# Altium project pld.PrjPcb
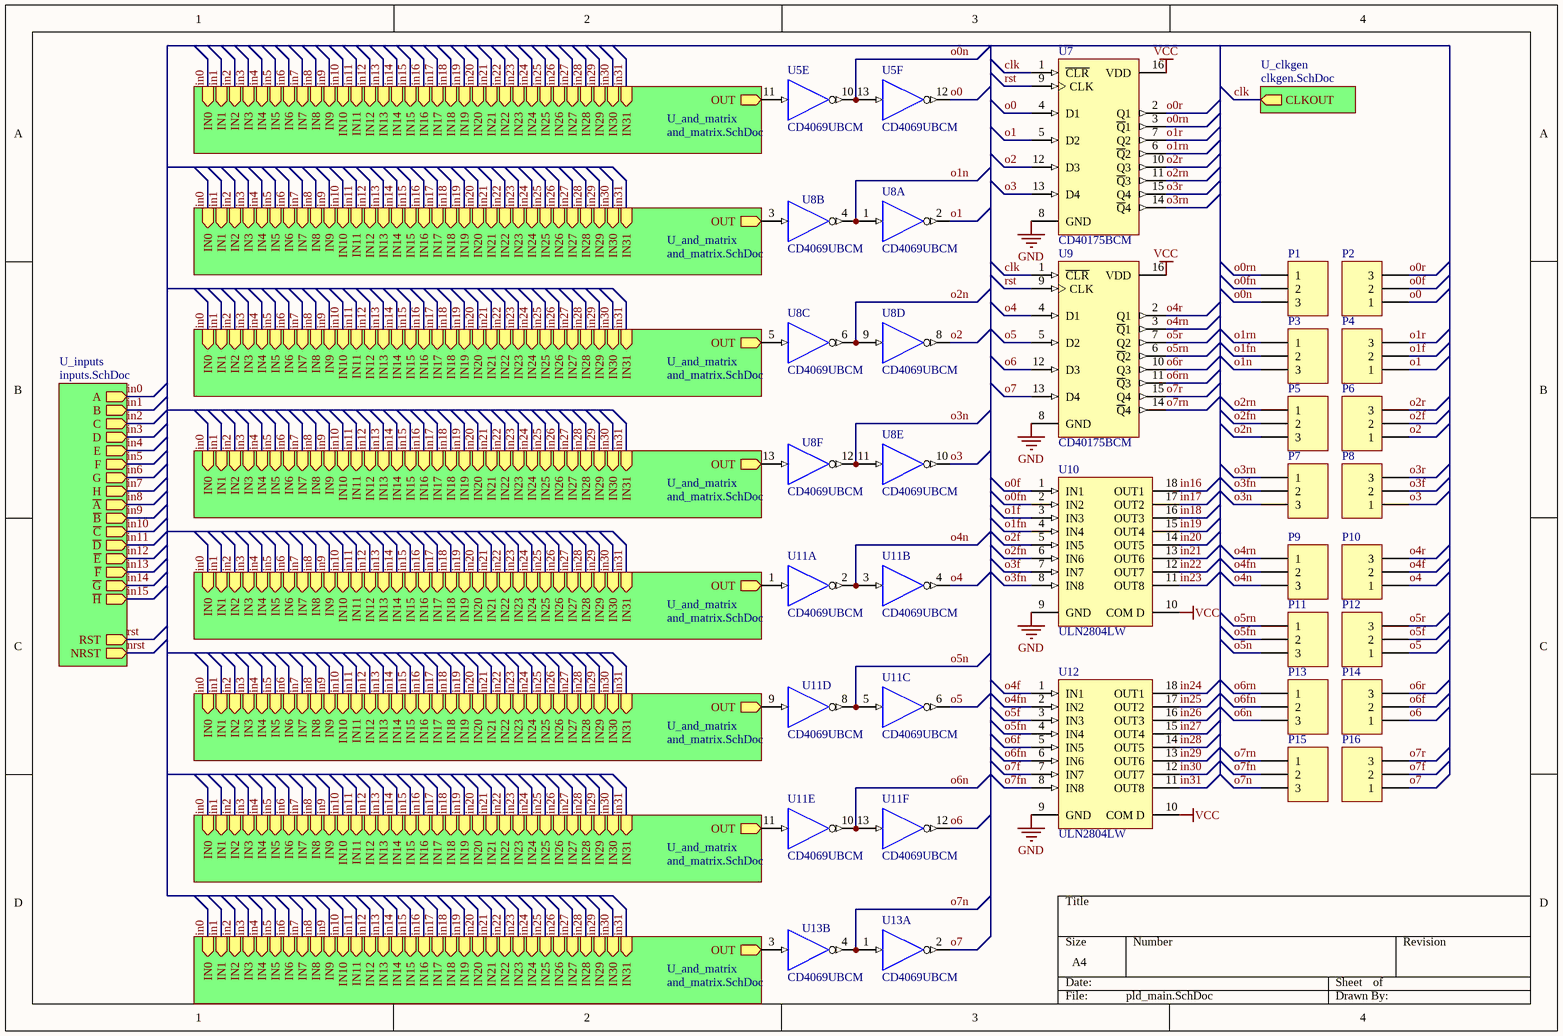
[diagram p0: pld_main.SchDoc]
4 sheets, 190 parts. Net scope: hierarchical (ports join the sheet entries above them; power ports are global).
Board file: pldpcb.PcbDoc
Sheets:
  pld_main.SchDoc
    U_inputs = inputs.SchDoc
    U_and_matrix = and_matrix.SchDoc
    U_and_matrix = and_matrix.SchDoc
    U_and_matrix = and_matrix.SchDoc
    U_and_matrix = and_matrix.SchDoc
    U_and_matrix = and_matrix.SchDoc
    U_and_matrix = and_matrix.SchDoc
    U_and_matrix = and_matrix.SchDoc
    U_and_matrix = and_matrix.SchDoc
    U_clkgen = clkgen.SchDoc

## Sheet pld_main.SchDoc
size A4

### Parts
(Parts that share a designator on the sheet are numbered #1, #2 ... from top to bottom, then left to right.)
P1  Header 3  [HDR1X3]  (value not drawn)
P2  Header 3  [HDR1X3]  (value not drawn)
P3  Header 3  [HDR1X3]  (value not drawn)
P4  Header 3  [HDR1X3]  (value not drawn)
P5  Header 3  [HDR1X3]  (value not drawn)
P6  Header 3  [HDR1X3]  (value not drawn)
P7  Header 3  [HDR1X3]  (value not drawn)
P8  Header 3  [HDR1X3]  (value not drawn)
P9  Header 3  [HDR1X3]  (value not drawn)
P10  Header 3  [HDR1X3]  (value not drawn)
P11  Header 3  [HDR1X3]  (value not drawn)
P12  Header 3  [HDR1X3]  (value not drawn)
P13  Header 3  [HDR1X3]  (value not drawn)
P14  Header 3  [HDR1X3]  (value not drawn)
P15  Header 3  [HDR1X3]  (value not drawn)
P16  Header 3  [HDR1X3]  (value not drawn)
U5#1  CD4069UBCM  [M14A_N]  (parts E,F of 6)
U7  CD40175BCM  [M16A_N]
U8  CD4069UBCM  [M14A_N]  (parts A,B,C,D,E,F of 6)
U9  CD40175BCM  [M16A_N]
U10  ULN2804LW  [LW18_L]
U11  CD4069UBCM  [M14A_N]  (parts A,B,C,D,E,F of 6)
U12  ULN2804LW  [LW18_L]
U13  CD4069UBCM  [M14A_N]  (parts A,B of 6)

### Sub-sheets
U_and_matrix = and_matrix.SchDoc: IN0 (in), IN1 (in), IN2 (in), IN3 (in), IN4 (in), IN5 (in), IN6 (in), IN7 (in), IN8 (in), IN9 (in), IN10 (in), IN11 (in), IN12 (in), IN13 (in), IN14 (in), IN15 (in), IN16 (in), IN17 (in), IN18 (in), IN19 (in), IN20 (in), IN21 (in), IN22 (in), IN23 (in), IN24 (in), IN25 (in), IN26 (in), IN27 (in), IN28 (in), IN29 (in), IN30 (in), IN31 (in), OUT (out)
U_and_matrix = and_matrix.SchDoc: IN0 (in), IN1 (in), IN2 (in), IN3 (in), IN4 (in), IN5 (in), IN6 (in), IN7 (in), IN8 (in), IN9 (in), IN10 (in), IN11 (in), IN12 (in), IN13 (in), IN14 (in), IN15 (in), IN16 (in), IN17 (in), IN18 (in), IN19 (in), IN20 (in), IN21 (in), IN22 (in), IN23 (in), IN24 (in), IN25 (in), IN26 (in), IN27 (in), IN28 (in), IN29 (in), IN30 (in), IN31 (in), OUT (out)
U_and_matrix = and_matrix.SchDoc: IN0 (in), IN1 (in), IN2 (in), IN3 (in), IN4 (in), IN5 (in), IN6 (in), IN7 (in), IN8 (in), IN9 (in), IN10 (in), IN11 (in), IN12 (in), IN13 (in), IN14 (in), IN15 (in), IN16 (in), IN17 (in), IN18 (in), IN19 (in), IN20 (in), IN21 (in), IN22 (in), IN23 (in), IN24 (in), IN25 (in), IN26 (in), IN27 (in), IN28 (in), IN29 (in), IN30 (in), IN31 (in), OUT (out)
U_and_matrix = and_matrix.SchDoc: IN0 (in), IN1 (in), IN2 (in), IN3 (in), IN4 (in), IN5 (in), IN6 (in), IN7 (in), IN8 (in), IN9 (in), IN10 (in), IN11 (in), IN12 (in), IN13 (in), IN14 (in), IN15 (in), IN16 (in), IN17 (in), IN18 (in), IN19 (in), IN20 (in), IN21 (in), IN22 (in), IN23 (in), IN24 (in), IN25 (in), IN26 (in), IN27 (in), IN28 (in), IN29 (in), IN30 (in), IN31 (in), OUT (out)
U_and_matrix = and_matrix.SchDoc: IN0 (in), IN1 (in), IN2 (in), IN3 (in), IN4 (in), IN5 (in), IN6 (in), IN7 (in), IN8 (in), IN9 (in), IN10 (in), IN11 (in), IN12 (in), IN13 (in), IN14 (in), IN15 (in), IN16 (in), IN17 (in), IN18 (in), IN19 (in), IN20 (in), IN21 (in), IN22 (in), IN23 (in), IN24 (in), IN25 (in), IN26 (in), IN27 (in), IN28 (in), IN29 (in), IN30 (in), IN31 (in), OUT (out)
U_and_matrix = and_matrix.SchDoc: IN0 (in), IN1 (in), IN2 (in), IN3 (in), IN4 (in), IN5 (in), IN6 (in), IN7 (in), IN8 (in), IN9 (in), IN10 (in), IN11 (in), IN12 (in), IN13 (in), IN14 (in), IN15 (in), IN16 (in), IN17 (in), IN18 (in), IN19 (in), IN20 (in), IN21 (in), IN22 (in), IN23 (in), IN24 (in), IN25 (in), IN26 (in), IN27 (in), IN28 (in), IN29 (in), IN30 (in), IN31 (in), OUT (out)
U_and_matrix = and_matrix.SchDoc: IN0 (in), IN1 (in), IN2 (in), IN3 (in), IN4 (in), IN5 (in), IN6 (in), IN7 (in), IN8 (in), IN9 (in), IN10 (in), IN11 (in), IN12 (in), IN13 (in), IN14 (in), IN15 (in), IN16 (in), IN17 (in), IN18 (in), IN19 (in), IN20 (in), IN21 (in), IN22 (in), IN23 (in), IN24 (in), IN25 (in), IN26 (in), IN27 (in), IN28 (in), IN29 (in), IN30 (in), IN31 (in), OUT (out)
U_and_matrix = and_matrix.SchDoc: IN0 (in), IN1 (in), IN2 (in), IN3 (in), IN4 (in), IN5 (in), IN6 (in), IN7 (in), IN8 (in), IN9 (in), IN10 (in), IN11 (in), IN12 (in), IN13 (in), IN14 (in), IN15 (in), IN16 (in), IN17 (in), IN18 (in), IN19 (in), IN20 (in), IN21 (in), IN22 (in), IN23 (in), IN24 (in), IN25 (in), IN26 (in), IN27 (in), IN28 (in), IN29 (in), IN30 (in), IN31 (in), OUT (out)
U_clkgen = clkgen.SchDoc: CLKOUT (out)
U_inputs = inputs.SchDoc: A (out), B (out), C (out), D (out), E (out), F (out), G (out), H (out), ~{A} (out), ~{B} (out), ~{C} (out), ~{D} (out), ~{E} (out), ~{F} (out), ~{G} (out), ~{H} (out), RST (out), NRST (out)

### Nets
GND: U5#1.7(GND) U7.8(GND) U8.7(GND) U9.8(GND) U10.9(GND) U11.7(GND) U12.9(GND) U13.7(GND)
VCC: U7.16(VDD) U9.16(VDD) U10.10(COM_D) U12.10(COM_D)
VDD: U5#1.14(VDD) U8.14(VDD) U11.14(VDD) U13.14(VDD)
clk: U7.1(~{CLR}) U9.1(~{CLR}) ; sheet U_clkgen/CLKOUT
in0: sheet U_inputs/A, sheet U_and_matrix/IN0, sheet U_and_matrix/IN0, sheet U_and_matrix/IN0, sheet U_and_matrix/IN0, sheet U_and_matrix/IN0, sheet U_and_matrix/IN0, sheet U_and_matrix/IN0, sheet U_and_matrix/IN0
in1: sheet U_inputs/B, sheet U_and_matrix/IN1, sheet U_and_matrix/IN1, sheet U_and_matrix/IN1, sheet U_and_matrix/IN1, sheet U_and_matrix/IN1, sheet U_and_matrix/IN1, sheet U_and_matrix/IN1, sheet U_and_matrix/IN1
in2: sheet U_inputs/C, sheet U_and_matrix/IN2, sheet U_and_matrix/IN2, sheet U_and_matrix/IN2, sheet U_and_matrix/IN2, sheet U_and_matrix/IN2, sheet U_and_matrix/IN2, sheet U_and_matrix/IN2, sheet U_and_matrix/IN2
in3: sheet U_inputs/D, sheet U_and_matrix/IN3, sheet U_and_matrix/IN3, sheet U_and_matrix/IN3, sheet U_and_matrix/IN3, sheet U_and_matrix/IN3, sheet U_and_matrix/IN3, sheet U_and_matrix/IN3, sheet U_and_matrix/IN3
in4: sheet U_inputs/E, sheet U_and_matrix/IN4, sheet U_and_matrix/IN4, sheet U_and_matrix/IN4, sheet U_and_matrix/IN4, sheet U_and_matrix/IN4, sheet U_and_matrix/IN4, sheet U_and_matrix/IN4, sheet U_and_matrix/IN4
in5: sheet U_inputs/F, sheet U_and_matrix/IN5, sheet U_and_matrix/IN5, sheet U_and_matrix/IN5, sheet U_and_matrix/IN5, sheet U_and_matrix/IN5, sheet U_and_matrix/IN5, sheet U_and_matrix/IN5, sheet U_and_matrix/IN5
in6: sheet U_inputs/G, sheet U_and_matrix/IN6, sheet U_and_matrix/IN6, sheet U_and_matrix/IN6, sheet U_and_matrix/IN6, sheet U_and_matrix/IN6, sheet U_and_matrix/IN6, sheet U_and_matrix/IN6, sheet U_and_matrix/IN6
in7: sheet U_inputs/H, sheet U_and_matrix/IN7, sheet U_and_matrix/IN7, sheet U_and_matrix/IN7, sheet U_and_matrix/IN7, sheet U_and_matrix/IN7, sheet U_and_matrix/IN7, sheet U_and_matrix/IN7, sheet U_and_matrix/IN7
in8: sheet U_inputs/~{A}, sheet U_and_matrix/IN8, sheet U_and_matrix/IN8, sheet U_and_matrix/IN8, sheet U_and_matrix/IN8, sheet U_and_matrix/IN8, sheet U_and_matrix/IN8, sheet U_and_matrix/IN8, sheet U_and_matrix/IN8
in9: sheet U_inputs/~{B}, sheet U_and_matrix/IN9, sheet U_and_matrix/IN9, sheet U_and_matrix/IN9, sheet U_and_matrix/IN9, sheet U_and_matrix/IN9, sheet U_and_matrix/IN9, sheet U_and_matrix/IN9, sheet U_and_matrix/IN9
in10: sheet U_inputs/~{C}, sheet U_and_matrix/IN10, sheet U_and_matrix/IN10, sheet U_and_matrix/IN10, sheet U_and_matrix/IN10, sheet U_and_matrix/IN10, sheet U_and_matrix/IN10, sheet U_and_matrix/IN10, sheet U_and_matrix/IN10
in11: sheet U_inputs/~{D}, sheet U_and_matrix/IN11, sheet U_and_matrix/IN11, sheet U_and_matrix/IN11, sheet U_and_matrix/IN11, sheet U_and_matrix/IN11, sheet U_and_matrix/IN11, sheet U_and_matrix/IN11, sheet U_and_matrix/IN11
in12: sheet U_inputs/~{E}, sheet U_and_matrix/IN12, sheet U_and_matrix/IN12, sheet U_and_matrix/IN12, sheet U_and_matrix/IN12, sheet U_and_matrix/IN12, sheet U_and_matrix/IN12, sheet U_and_matrix/IN12, sheet U_and_matrix/IN12
in13: sheet U_inputs/~{F}, sheet U_and_matrix/IN13, sheet U_and_matrix/IN13, sheet U_and_matrix/IN13, sheet U_and_matrix/IN13, sheet U_and_matrix/IN13, sheet U_and_matrix/IN13, sheet U_and_matrix/IN13, sheet U_and_matrix/IN13
in14: sheet U_inputs/~{G}, sheet U_and_matrix/IN14, sheet U_and_matrix/IN14, sheet U_and_matrix/IN14, sheet U_and_matrix/IN14, sheet U_and_matrix/IN14, sheet U_and_matrix/IN14, sheet U_and_matrix/IN14, sheet U_and_matrix/IN14
in15: sheet U_inputs/~{H}, sheet U_and_matrix/IN15, sheet U_and_matrix/IN15, sheet U_and_matrix/IN15, sheet U_and_matrix/IN15, sheet U_and_matrix/IN15, sheet U_and_matrix/IN15, sheet U_and_matrix/IN15, sheet U_and_matrix/IN15
in16: U10.18(OUT1) ; sheet U_and_matrix/IN16, sheet U_and_matrix/IN16, sheet U_and_matrix/IN16, sheet U_and_matrix/IN16, sheet U_and_matrix/IN16, sheet U_and_matrix/IN16, sheet U_and_matrix/IN16, sheet U_and_matrix/IN16
in17: U10.17(OUT2) ; sheet U_and_matrix/IN17, sheet U_and_matrix/IN17, sheet U_and_matrix/IN17, sheet U_and_matrix/IN17, sheet U_and_matrix/IN17, sheet U_and_matrix/IN17, sheet U_and_matrix/IN17, sheet U_and_matrix/IN17
in18: U10.16(OUT3) ; sheet U_and_matrix/IN18, sheet U_and_matrix/IN18, sheet U_and_matrix/IN18, sheet U_and_matrix/IN18, sheet U_and_matrix/IN18, sheet U_and_matrix/IN18, sheet U_and_matrix/IN18, sheet U_and_matrix/IN18
in19: U10.15(OUT4) ; sheet U_and_matrix/IN19, sheet U_and_matrix/IN19, sheet U_and_matrix/IN19, sheet U_and_matrix/IN19, sheet U_and_matrix/IN19, sheet U_and_matrix/IN19, sheet U_and_matrix/IN19, sheet U_and_matrix/IN19
in20: U10.14(OUT5) ; sheet U_and_matrix/IN20, sheet U_and_matrix/IN20, sheet U_and_matrix/IN20, sheet U_and_matrix/IN20, sheet U_and_matrix/IN20, sheet U_and_matrix/IN20, sheet U_and_matrix/IN20, sheet U_and_matrix/IN20
in21: U10.13(OUT6) ; sheet U_and_matrix/IN21, sheet U_and_matrix/IN21, sheet U_and_matrix/IN21, sheet U_and_matrix/IN21, sheet U_and_matrix/IN21, sheet U_and_matrix/IN21, sheet U_and_matrix/IN21, sheet U_and_matrix/IN21
in22: U10.12(OUT7) ; sheet U_and_matrix/IN22, sheet U_and_matrix/IN22, sheet U_and_matrix/IN22, sheet U_and_matrix/IN22, sheet U_and_matrix/IN22, sheet U_and_matrix/IN22, sheet U_and_matrix/IN22, sheet U_and_matrix/IN22
in23: U10.11(OUT8) ; sheet U_and_matrix/IN23, sheet U_and_matrix/IN23, sheet U_and_matrix/IN23, sheet U_and_matrix/IN23, sheet U_and_matrix/IN23, sheet U_and_matrix/IN23, sheet U_and_matrix/IN23, sheet U_and_matrix/IN23
in24: U12.18(OUT1) ; sheet U_and_matrix/IN24, sheet U_and_matrix/IN24, sheet U_and_matrix/IN24, sheet U_and_matrix/IN24, sheet U_and_matrix/IN24, sheet U_and_matrix/IN24, sheet U_and_matrix/IN24, sheet U_and_matrix/IN24
in25: U12.17(OUT2) ; sheet U_and_matrix/IN25, sheet U_and_matrix/IN25, sheet U_and_matrix/IN25, sheet U_and_matrix/IN25, sheet U_and_matrix/IN25, sheet U_and_matrix/IN25, sheet U_and_matrix/IN25, sheet U_and_matrix/IN25
in26: U12.16(OUT3) ; sheet U_and_matrix/IN26, sheet U_and_matrix/IN26, sheet U_and_matrix/IN26, sheet U_and_matrix/IN26, sheet U_and_matrix/IN26, sheet U_and_matrix/IN26, sheet U_and_matrix/IN26, sheet U_and_matrix/IN26
in27: U12.15(OUT4) ; sheet U_and_matrix/IN27, sheet U_and_matrix/IN27, sheet U_and_matrix/IN27, sheet U_and_matrix/IN27, sheet U_and_matrix/IN27, sheet U_and_matrix/IN27, sheet U_and_matrix/IN27, sheet U_and_matrix/IN27
in28: U12.14(OUT5) ; sheet U_and_matrix/IN28, sheet U_and_matrix/IN28, sheet U_and_matrix/IN28, sheet U_and_matrix/IN28, sheet U_and_matrix/IN28, sheet U_and_matrix/IN28, sheet U_and_matrix/IN28, sheet U_and_matrix/IN28
in29: U12.13(OUT6) ; sheet U_and_matrix/IN29, sheet U_and_matrix/IN29, sheet U_and_matrix/IN29, sheet U_and_matrix/IN29, sheet U_and_matrix/IN29, sheet U_and_matrix/IN29, sheet U_and_matrix/IN29, sheet U_and_matrix/IN29
in30: U12.12(OUT7) ; sheet U_and_matrix/IN30, sheet U_and_matrix/IN30, sheet U_and_matrix/IN30, sheet U_and_matrix/IN30, sheet U_and_matrix/IN30, sheet U_and_matrix/IN30, sheet U_and_matrix/IN30, sheet U_and_matrix/IN30
in31: U12.11(OUT8) ; sheet U_and_matrix/IN31, sheet U_and_matrix/IN31, sheet U_and_matrix/IN31, sheet U_and_matrix/IN31, sheet U_and_matrix/IN31, sheet U_and_matrix/IN31, sheet U_and_matrix/IN31, sheet U_and_matrix/IN31
o0: P2.1 U5#1.12(O) U7.4(D1)
o0f: P2.2 U10.1(IN1)
o0fn: P1.2 U10.2(IN2)
o0n: P1.3 U5#1.10(O) U5#1.13(I)
o0r: P2.3 U7.2(Q1)
o0rn: P1.1 U7.3(~{Q}1)
o1: P4.1 U7.5(D2) U8.2(O)
o1f: P4.2 U10.3(IN3)
o1fn: P3.2 U10.4(IN4)
o1n: P3.3 U8.1(I) U8.4(O)
o1r: P4.3 U7.7(Q2)
o1rn: P3.1 U7.6(~{Q}2)
o2: P6.1 U7.12(D3) U8.8(O)
o2f: P6.2 U10.5(IN5)
o2fn: P5.2 U10.6(IN6)
o2n: P5.3 U8.6(O) U8.9(I)
o2r: P6.3 U7.10(Q3)
o2rn: P5.1 U7.11(~{Q}3)
o3: P8.1 U7.13(D4) U8.10(O)
o3f: P8.2 U10.7(IN7)
o3fn: P7.2 U10.8(IN8)
o3n: P7.3 U8.11(I) U8.12(O)
o3r: P8.3 U7.15(Q4)
o3rn: P7.1 U7.14(~{Q}4)
o4: P10.1 U9.4(D1) U11.4(O)
o4f: P10.2 U12.1(IN1)
o4fn: P9.2 U12.2(IN2)
o4n: P9.3 U11.2(O) U11.3(I)
o4r: P10.3 U9.2(Q1)
o4rn: P9.1 U9.3(~{Q}1)
o5: P12.1 U9.5(D2) U11.6(O)
o5f: P12.2 U12.3(IN3)
o5fn: P11.2 U12.4(IN4)
o5n: P11.3 U11.5(I) U11.8(O)
o5r: P12.3 U9.7(Q2)
o5rn: P11.1 U9.6(~{Q}2)
o6: P14.1 U9.12(D3) U11.12(O)
o6f: P14.2 U12.5(IN5)
o6fn: P13.2 U12.6(IN6)
o6n: P13.3 U11.10(O) U11.13(I)
o6r: P14.3 U9.10(Q3)
o6rn: P13.1 U9.11(~{Q}3)
o7: P16.1 U9.13(D4) U13.2(O)
o7f: P16.2 U12.7(IN7)
o7fn: P15.2 U12.8(IN8)
o7n: P15.3 U13.1(I) U13.4(O)
o7r: P16.3 U9.15(Q4)
o7rn: P15.1 U9.14(~{Q}4)
rst: U7.9(CLK) U9.9(CLK) ; sheet U_inputs/RST
NetR9_U_and_matrix#1_2: U5#1.11(I) ; sheet U_and_matrix/OUT
NetR9_U_and_matrix#2_2: U8.3(I) ; sheet U_and_matrix/OUT
NetR9_U_and_matrix#3_2: U8.5(I) ; sheet U_and_matrix/OUT
NetR9_U_and_matrix#4_2: U8.13(I) ; sheet U_and_matrix/OUT
NetR9_U_and_matrix#5_2: U11.1(I) ; sheet U_and_matrix/OUT
NetR9_U_and_matrix#6_2: U11.9(I) ; sheet U_and_matrix/OUT
NetR9_U_and_matrix#7_2: U11.11(I) ; sheet U_and_matrix/OUT
NetR9_U_and_matrix#8_2: U13.3(I) ; sheet U_and_matrix/OUT

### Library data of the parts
P1-P16 = Header 3: Header, 3-Pin
U5#1 U8 U11 U13 = CD4069UBCM: Inverted Circuits
U7 U9 = CD40175BCM: Quad D-Type Flip-Flop
U10 U12 = ULN2804LW: High-Voltage, High-Current Darlington Array

## Sheet inputs.SchDoc
size A4
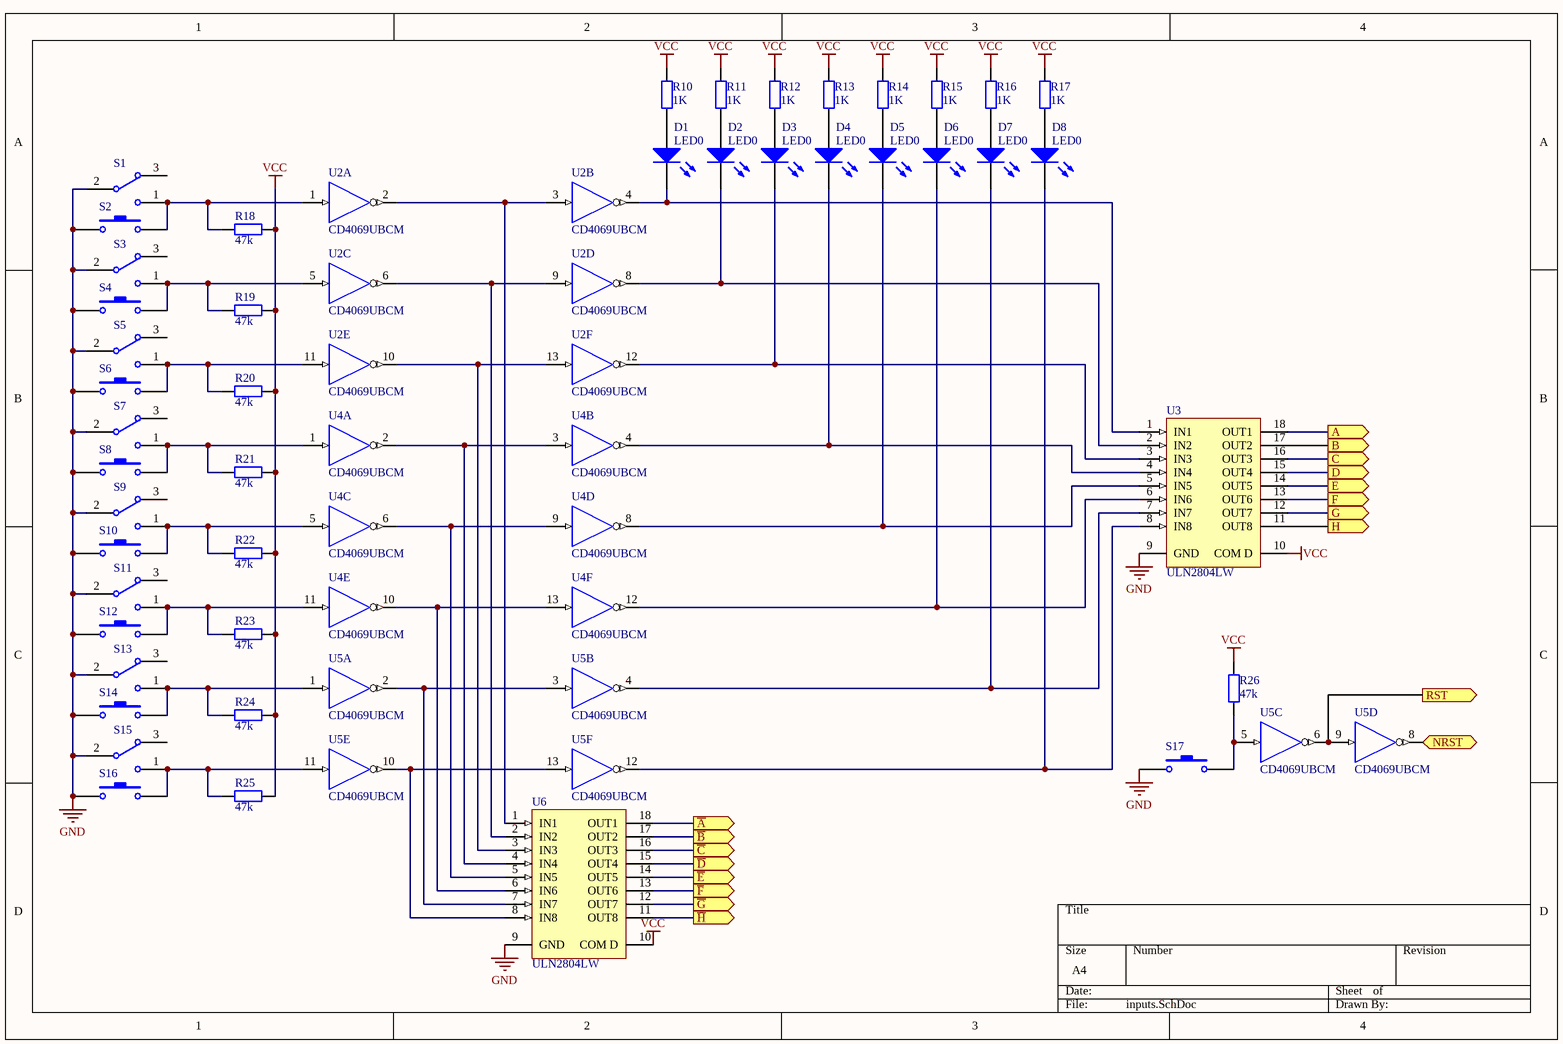
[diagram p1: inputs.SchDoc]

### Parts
(Parts that share a designator on the sheet are numbered #1, #2 ... from top to bottom, then left to right.)
D1  LED0  [LED-0]
D2  LED0  [LED-0]
D3  LED0  [LED-0]
D4  LED0  [LED-0]
D5  LED0  [LED-0]
D6  LED0  [LED-0]
D7  LED0  [LED-0]
D8  LED0  [LED-0]
R10  value 1K  [AXIAL-0.4]  (hidden comment: Res2)
R11  value 1K  [AXIAL-0.4]  (hidden comment: Res2)
R12  value 1K  [AXIAL-0.4]  (hidden comment: Res2)
R13  value 1K  [AXIAL-0.4]  (hidden comment: Res2)
R14  value 1K  [AXIAL-0.4]  (hidden comment: Res2)
R15  value 1K  [AXIAL-0.4]  (hidden comment: Res2)
R16  value 1K  [AXIAL-0.4]  (hidden comment: Res2)
R17  value 1K  [AXIAL-0.4]  (hidden comment: Res2)
R18  value 47k  [AXIAL-0.4]  (hidden comment: Res2)
R19  value 47k  [AXIAL-0.4]  (hidden comment: Res2)
R20  value 47k  [AXIAL-0.4]  (hidden comment: Res2)
R21  value 47k  [AXIAL-0.4]  (hidden comment: Res2)
R22  value 47k  [AXIAL-0.4]  (hidden comment: Res2)
R23  value 47k  [AXIAL-0.4]  (hidden comment: Res2)
R24  value 47k  [AXIAL-0.4]  (hidden comment: Res2)
R25  value 47k  [AXIAL-0.4]  (hidden comment: Res2)
R26  value 47k  [AXIAL-0.4]  (hidden comment: Res2)
S1  SW-SPDT  [TL36WW15050]  (value not drawn)
S2  SW-PB  [SPST-2]  (value not drawn)
S3  SW-SPDT  [TL36WW15050]  (value not drawn)
S4  SW-PB  [SPST-2]  (value not drawn)
S5  SW-SPDT  [TL36WW15050]  (value not drawn)
S6  SW-PB  [SPST-2]  (value not drawn)
S7  SW-SPDT  [TL36WW15050]  (value not drawn)
S8  SW-PB  [SPST-2]  (value not drawn)
S9  SW-SPDT  [TL36WW15050]  (value not drawn)
S10  SW-PB  [SPST-2]  (value not drawn)
S11  SW-SPDT  [TL36WW15050]  (value not drawn)
S12  SW-PB  [SPST-2]  (value not drawn)
S13  SW-SPDT  [TL36WW15050]  (value not drawn)
S14  SW-PB  [SPST-2]  (value not drawn)
S15  SW-SPDT  [TL36WW15050]  (value not drawn)
S16  SW-PB  [SPST-2]  (value not drawn)
S17  SW-PB  [SPST-2]  (value not drawn)
U2  CD4069UBCM  [M14A_N]  (parts A,B,C,D,E,F of 6)
U3  ULN2804LW  [LW18_L]
U4  CD4069UBCM  [M14A_N]  (parts A,B,C,D,E,F of 6)
U5#1  CD4069UBCM  [M14A_N]  (parts A,B,C,D of 6)
U5#2  CD4069UBCM  [M14A_N]  (parts E,F of 6)
U6  ULN2804LW  [LW18_L]

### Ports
A (out), B (out), C (out), D (out), E (out), F (out), G (out), H (out), NRST (out), RST (out), ~{A} (out), ~{B} (out), ~{C} (out), ~{D} (out), ~{E} (out), ~{F} (out), ~{G} (out), ~{H} (out)

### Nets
GND: S1.2 S2.1 S3.2 S4.1 S5.2 S6.1 S7.2 S8.1 S9.2 S10.1 S11.2 S12.1 S13.2 S14.1 S15.2 S16.1 S17.1 U2.7(GND) U3.9(GND) U4.7(GND) U5#1.7(GND) U5#2.7(GND) U6.9(GND)
VCC: R10.1 R11.1 R12.1 R13.1 R14.1 R15.1 R16.1 R17.1 R18.2 R19.2 R20.2 R21.2 R22.2 R23.2 R24.2 R25.2 R26.2 U3.10(COM_D) U6.10(COM_D)
VDD: U2.14(VDD) U4.14(VDD) U5#1.14(VDD) U5#2.14(VDD)
in0: U3.18(OUT1) ; port A
in1: U3.17(OUT2) ; port B
in2: U3.16(OUT3) ; port C
in3: U3.15(OUT4) ; port D
in4: U3.14(OUT5) ; port E
in5: U3.13(OUT6) ; port F
in6: U3.12(OUT7) ; port G
in7: U3.11(OUT8) ; port H
in8: U6.18(OUT1) ; port ~{A}
in9: U6.17(OUT2) ; port ~{B}
in10: U6.16(OUT3) ; port ~{C}
in11: U6.15(OUT4) ; port ~{D}
in12: U6.14(OUT5) ; port ~{E}
in13: U6.13(OUT6) ; port ~{F}
in14: U6.12(OUT7) ; port ~{G}
in15: U6.11(OUT8) ; port ~{H}
nrst: U5#1.8(O) ; port NRST
rst: U5#1.6(O) U5#1.9(I) ; port RST
NetD1_1: D1.1(A) R10.2
NetD1_2: D1.2(K) U2.4(O) U3.1(IN1)
NetD2_1: D2.1(A) R11.2
NetD2_2: D2.2(K) U2.8(O) U3.2(IN2)
NetD3_1: D3.1(A) R12.2
NetD3_2: D3.2(K) U2.12(O) U3.3(IN3)
NetD4_1: D4.1(A) R13.2
NetD4_2: D4.2(K) U3.4(IN4) U4.4(O)
NetD5_1: D5.1(A) R14.2
NetD5_2: D5.2(K) U3.5(IN5) U4.8(O)
NetD6_1: D6.1(A) R15.2
NetD6_2: D6.2(K) U3.6(IN6) U4.12(O)
NetD7_1: D7.1(A) R16.2
NetD7_2: D7.2(K) U3.7(IN7) U5#1.4(O)
NetD8_1: D8.1(A) R17.2
NetD8_2: D8.2(K) U3.8(IN8) U5#2.12(O)
NetR18_1: R18.1 S1.1 S2.2 U2.1(I)
NetR19_1: R19.1 S3.1 S4.2 U2.5(I)
NetR20_1: R20.1 S5.1 S6.2 U2.11(I)
NetR21_1: R21.1 S7.1 S8.2 U4.1(I)
NetR22_1: R22.1 S9.1 S10.2 U4.5(I)
NetR23_1: R23.1 S11.1 S12.2 U4.11(I)
NetR24_1: R24.1 S13.1 S14.2 U5#1.1(I)
NetR25_1: R25.1 S15.1 S16.2 U5#2.11(I)
NetR26_1: R26.1 S17.2 U5#1.5(I)
NetU2_2: U2.2(O) U2.3(I) U6.1(IN1)
NetU2_6: U2.6(O) U2.9(I) U6.2(IN2)
NetU2_10: U2.10(O) U2.13(I) U6.3(IN3)
NetU4_2: U4.2(O) U4.3(I) U6.4(IN4)
NetU4_6: U4.6(O) U4.9(I) U6.5(IN5)
NetU4_10: U4.10(O) U4.13(I) U6.6(IN6)
NetU5#1_2: U5#1.2(O) U5#1.3(I) U6.7(IN7)
NetU5#2_10: U5#2.10(O) U5#2.13(I) U6.8(IN8)

Not connected (* = marked no-connect by the designer): S1 3; S3 3; S5 3; S7 3; S9 3; S11 3; S13 3; S15 3

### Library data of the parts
D1-D8 = LED0: Typical INFRARED GaAs LED
R10-R26 = Res2: Resistor
S1 S3 S5 S7 S9 S11 S13 S15 = SW-SPDT: SPDT Subminiature Toggle Switch, Right Angle Mounting, Vertical Actuation
S2 S4 S6 S8 S10 S12 S14 S16 S17 = SW-PB: Switch
U2 U4 U5#1 U5#2 = CD4069UBCM: Inverted Circuits
U3 U6 = ULN2804LW: as U10 on sheet pld_main

## Sheet and_matrix.SchDoc
size 317 x 193 mm
Used 8 times, as channels U_and_matrix, U_and_matrix, U_and_matrix, U_and_matrix, U_and_matrix, U_and_matrix, U_and_matrix, U_and_matrix. Parts and nets are listed once, with the designators drawn on the sheet.
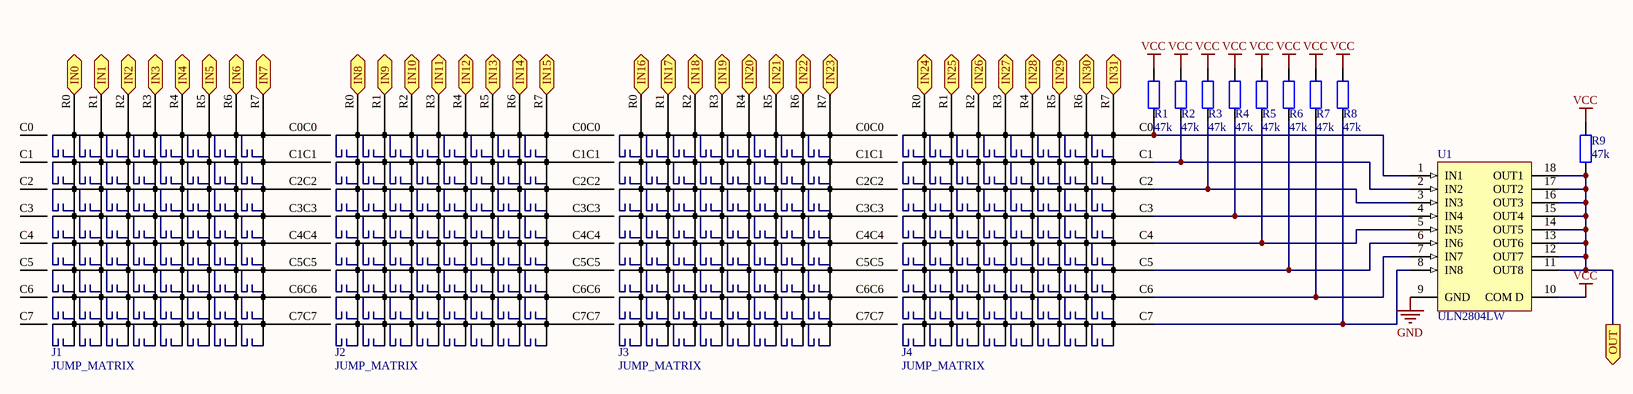
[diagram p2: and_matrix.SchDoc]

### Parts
J1  JUMP_MATRIX  [JUMP_MATRIX]
J2  JUMP_MATRIX  [JUMP_MATRIX]
J3  JUMP_MATRIX  [JUMP_MATRIX]
J4  JUMP_MATRIX  [JUMP_MATRIX]
R1  value 47k  [C0805]  (hidden comment: Res2)
R2  value 47k  [C0805]  (hidden comment: Res2)
R3  value 47k  [C0805]  (hidden comment: Res2)
R4  value 47k  [C0805]  (hidden comment: Res2)
R5  value 47k  [C0805]  (hidden comment: Res2)
R6  value 47k  [C0805]  (hidden comment: Res2)
R7  value 47k  [C0805]  (hidden comment: Res2)
R8  value 47k  [C0805]  (hidden comment: Res2)
R9  value 47k  [C0805]  (hidden comment: Res2)
U1  ULN2804LW  [LW18_L]

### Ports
IN0 (in), IN1 (in), IN2 (in), IN3 (in), IN4 (in), IN5 (in), IN6 (in), IN7 (in), IN8 (in), IN9 (in), IN10 (in), IN11 (in), IN12 (in), IN13 (in), IN14 (in), IN15 (in), IN16 (in), IN17 (in), IN18 (in), IN19 (in), IN20 (in), IN21 (in), IN22 (in), IN23 (in), IN24 (in), IN25 (in), IN26 (in), IN27 (in), IN28 (in), IN29 (in), IN30 (in), IN31 (in), OUT (out)

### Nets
GND: U1.9(GND)
VCC: R1.2 R2.2 R3.2 R4.2 R5.2 R6.2 R7.2 R8.2 R9.1 U1.10(COM_D)
IN0: J1.R0 ; port IN0
IN1: J1.R1 ; port IN1
IN2: J1.R2 ; port IN2
IN3: J1.R3 ; port IN3
IN4: J1.R4 ; port IN4
IN5: J1.R5 ; port IN5
IN6: J1.R6 ; port IN6
IN7: J1.R7 ; port IN7
IN8: J2.R0 ; port IN8
IN9: J2.R1 ; port IN9
IN10: J2.R2 ; port IN10
IN11: J2.R3 ; port IN11
IN12: J2.R4 ; port IN12
IN13: J2.R5 ; port IN13
IN14: J2.R6 ; port IN14
IN15: J2.R7 ; port IN15
IN16: J3.R0 ; port IN16
IN17: J3.R1 ; port IN17
IN18: J3.R2 ; port IN18
IN19: J3.R3 ; port IN19
IN20: J3.R4 ; port IN20
IN21: J3.R5 ; port IN21
IN22: J3.R6 ; port IN22
IN23: J3.R7 ; port IN23
IN24: J4.R0 ; port IN24
IN25: J4.R1 ; port IN25
IN26: J4.R2 ; port IN26
IN27: J4.R3 ; port IN27
IN28: J4.R4 ; port IN28
IN29: J4.R5 ; port IN29
IN30: J4.R6 ; port IN30
IN31: J4.R7 ; port IN31
OUT: R9.2 U1.11(OUT8) U1.12(OUT7) U1.13(OUT6) U1.14(OUT5) U1.15(OUT4) U1.16(OUT3) U1.17(OUT2) U1.18(OUT1) ; port OUT
NetJ1_C0: J1.C0 J2.C0
NetJ1_C1: J1.C1 J2.C1
NetJ1_C2: J1.C2 J2.C2
NetJ1_C3: J1.C3 J2.C3
NetJ1_C4: J1.C4 J2.C4
NetJ1_C5: J1.C5 J2.C5
NetJ1_C6: J1.C6 J2.C6
NetJ1_C7: J1.C7 J2.C7
NetJ2_C0: J2.C0 J3.C0
NetJ2_C1: J2.C1 J3.C1
NetJ2_C2: J2.C2 J3.C2
NetJ2_C3: J2.C3 J3.C3
NetJ2_C4: J2.C4 J3.C4
NetJ2_C5: J2.C5 J3.C5
NetJ2_C6: J2.C6 J3.C6
NetJ2_C7: J2.C7 J3.C7
NetJ3_C0: J3.C0 J4.C0
NetJ3_C1: J3.C1 J4.C1
NetJ3_C2: J3.C2 J4.C2
NetJ3_C3: J3.C3 J4.C3
NetJ3_C4: J3.C4 J4.C4
NetJ3_C5: J3.C5 J4.C5
NetJ3_C6: J3.C6 J4.C6
NetJ3_C7: J3.C7 J4.C7
NetJ4_C0: J4.C0 R1.1 U1.1(IN1)
NetJ4_C1: J4.C1 R2.1 U1.2(IN2)
NetJ4_C2: J4.C2 R3.1 U1.3(IN3)
NetJ4_C3: J4.C3 R4.1 U1.4(IN4)
NetJ4_C4: J4.C4 R5.1 U1.5(IN5)
NetJ4_C5: J4.C5 R6.1 U1.6(IN6)
NetJ4_C6: J4.C6 R7.1 U1.7(IN7)
NetJ4_C7: J4.C7 R8.1 U1.8(IN8)

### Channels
U_and_matrix: designators end in _U_and_matrix#1; ports IN0=in0 IN1=in1 IN2=in2 IN3=in3 IN4=in4 IN5=in5 IN6=in6 IN7=in7 IN8=in8 IN9=in9 IN10=in10 IN11=in11 IN12=in12 IN13=in13 IN14=in14 IN15=in15 IN16=in16 IN17=in17 IN18=in18 IN19=in19 IN20=in20 IN21=in21 IN22=in22 IN23=in23 IN24=in24 IN25=in25 IN26=in26 IN27=in27 IN28=in28 IN29=in29 IN30=in30 IN31=in31 OUT=NetR9_U_and_matrix#1_2
U_and_matrix: designators end in _U_and_matrix#2; ports IN0=in0 IN1=in1 IN2=in2 IN3=in3 IN4=in4 IN5=in5 IN6=in6 IN7=in7 IN8=in8 IN9=in9 IN10=in10 IN11=in11 IN12=in12 IN13=in13 IN14=in14 IN15=in15 IN16=in16 IN17=in17 IN18=in18 IN19=in19 IN20=in20 IN21=in21 IN22=in22 IN23=in23 IN24=in24 IN25=in25 IN26=in26 IN27=in27 IN28=in28 IN29=in29 IN30=in30 IN31=in31 OUT=NetR9_U_and_matrix#2_2
U_and_matrix: designators end in _U_and_matrix#3; ports IN0=in0 IN1=in1 IN2=in2 IN3=in3 IN4=in4 IN5=in5 IN6=in6 IN7=in7 IN8=in8 IN9=in9 IN10=in10 IN11=in11 IN12=in12 IN13=in13 IN14=in14 IN15=in15 IN16=in16 IN17=in17 IN18=in18 IN19=in19 IN20=in20 IN21=in21 IN22=in22 IN23=in23 IN24=in24 IN25=in25 IN26=in26 IN27=in27 IN28=in28 IN29=in29 IN30=in30 IN31=in31 OUT=NetR9_U_and_matrix#3_2
U_and_matrix: designators end in _U_and_matrix#4; ports IN0=in0 IN1=in1 IN2=in2 IN3=in3 IN4=in4 IN5=in5 IN6=in6 IN7=in7 IN8=in8 IN9=in9 IN10=in10 IN11=in11 IN12=in12 IN13=in13 IN14=in14 IN15=in15 IN16=in16 IN17=in17 IN18=in18 IN19=in19 IN20=in20 IN21=in21 IN22=in22 IN23=in23 IN24=in24 IN25=in25 IN26=in26 IN27=in27 IN28=in28 IN29=in29 IN30=in30 IN31=in31 OUT=NetR9_U_and_matrix#4_2
U_and_matrix: designators end in _U_and_matrix#5; ports IN0=in0 IN1=in1 IN2=in2 IN3=in3 IN4=in4 IN5=in5 IN6=in6 IN7=in7 IN8=in8 IN9=in9 IN10=in10 IN11=in11 IN12=in12 IN13=in13 IN14=in14 IN15=in15 IN16=in16 IN17=in17 IN18=in18 IN19=in19 IN20=in20 IN21=in21 IN22=in22 IN23=in23 IN24=in24 IN25=in25 IN26=in26 IN27=in27 IN28=in28 IN29=in29 IN30=in30 IN31=in31 OUT=NetR9_U_and_matrix#5_2
U_and_matrix: designators end in _U_and_matrix#6; ports IN0=in0 IN1=in1 IN2=in2 IN3=in3 IN4=in4 IN5=in5 IN6=in6 IN7=in7 IN8=in8 IN9=in9 IN10=in10 IN11=in11 IN12=in12 IN13=in13 IN14=in14 IN15=in15 IN16=in16 IN17=in17 IN18=in18 IN19=in19 IN20=in20 IN21=in21 IN22=in22 IN23=in23 IN24=in24 IN25=in25 IN26=in26 IN27=in27 IN28=in28 IN29=in29 IN30=in30 IN31=in31 OUT=NetR9_U_and_matrix#6_2
U_and_matrix: designators end in _U_and_matrix#7; ports IN0=in0 IN1=in1 IN2=in2 IN3=in3 IN4=in4 IN5=in5 IN6=in6 IN7=in7 IN8=in8 IN9=in9 IN10=in10 IN11=in11 IN12=in12 IN13=in13 IN14=in14 IN15=in15 IN16=in16 IN17=in17 IN18=in18 IN19=in19 IN20=in20 IN21=in21 IN22=in22 IN23=in23 IN24=in24 IN25=in25 IN26=in26 IN27=in27 IN28=in28 IN29=in29 IN30=in30 IN31=in31 OUT=NetR9_U_and_matrix#7_2
U_and_matrix: designators end in _U_and_matrix#8; ports IN0=in0 IN1=in1 IN2=in2 IN3=in3 IN4=in4 IN5=in5 IN6=in6 IN7=in7 IN8=in8 IN9=in9 IN10=in10 IN11=in11 IN12=in12 IN13=in13 IN14=in14 IN15=in15 IN16=in16 IN17=in17 IN18=in18 IN19=in19 IN20=in20 IN21=in21 IN22=in22 IN23=in23 IN24=in24 IN25=in25 IN26=in26 IN27=in27 IN28=in28 IN29=in29 IN30=in30 IN31=in31 OUT=NetR9_U_and_matrix#8_2

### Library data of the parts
R1-R9 = Res2: Resistor
U1 = ULN2804LW: as U10 on sheet pld_main

## Sheet clkgen.SchDoc
size A4
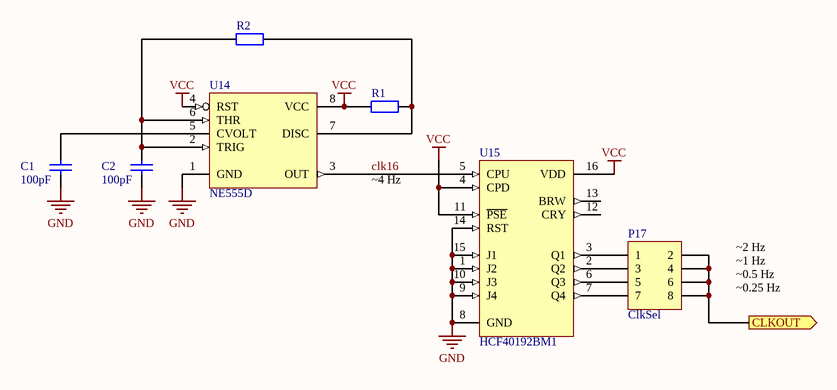
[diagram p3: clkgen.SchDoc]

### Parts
C1  value 100pF  [RAD-0.3]  (hidden comment: Cap)
C2  value 100pF  [RAD-0.3]  (hidden comment: Cap)
P17  ClkSel  [HDR2X4]
R1  Res2  [C0805]  (value not drawn)
R2  Res2  [C0805]  (value not drawn)
U14  NE555D  [D008_L]
U15  HCF40192BM1  [SO16_N]

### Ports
CLKOUT (out)

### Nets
GND: C1.2 C2.2 U14.1(GND) U15.1(J2) U15.8(GND) U15.9(J4) U15.10(J3) U15.14(RST) U15.15(J1)
VCC: R1.2 U14.4(RST) U14.8(VCC) U15.4(CPD) U15.11(~{PSE}) U15.16(VDD)
clk: P17.2 P17.4 P17.6 P17.8 ; port CLKOUT
clk16: U14.3(OUT) U15.5(CPU)
NetC1_1: C1.1 U14.5(CVOLT)
NetC2_1: C2.1 R2.2 U14.2(TRIG) U14.6(THR)
NetP17_1: P17.1 U15.3(Q1)
NetP17_3: P17.3 U15.2(Q2)
NetP17_5: P17.5 U15.6(Q3)
NetP17_7: P17.7 U15.7(Q4)
NetR1_1: R1.1 R2.1 U14.7(DISC)

Not connected (* = marked no-connect by the designer): U15 12(CRY) 13(BRW)

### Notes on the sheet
- ~4 Hz
- | Hz
- ~0.5 Hz
- Hz
- ~0.25 Hz

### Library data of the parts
C1 C2 = Cap: Capacitor
P17 = Header 4X2: Header, 4-Pin, Dual row
R1 R2 = Res2: Resistor
U14 = NE555D: Precision Timer
U15 = HCF40192BM1: Presettable Up/Down Counter (Dual Clock with Reset) BCD Type

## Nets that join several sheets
GND: pld_main (8 pins), inputs (23 pins), U_and_matrix (U1_U_and_matrix#1.9), U_and_matrix (U1_U_and_matrix#2.9), U_and_matrix (U1_U_and_matrix#3.9), U_and_matrix (U1_U_and_matrix#4.9), U_and_matrix (U1_U_and_matrix#5.9), U_and_matrix (U1_U_and_matrix#6.9), U_and_matrix (U1_U_and_matrix#7.9), U_and_matrix (U1_U_and_matrix#8.9), clkgen (9 pins)
VCC: pld_main (U7.16 U9.16 U10.10 U12.10), inputs (19 pins), U_and_matrix (10 pins), U_and_matrix (10 pins), U_and_matrix (10 pins), U_and_matrix (10 pins), U_and_matrix (10 pins), U_and_matrix (10 pins), U_and_matrix (10 pins), U_and_matrix (10 pins), clkgen (6 pins)
VDD: pld_main (U5#1.14 U8.14 U11.14 U13.14), inputs (U2.14 U4.14 U5#1.14 U5#2.14)
clk: pld_main (U7.1 U9.1), clkgen (P17.2 P17.4 P17.6 P17.8)
in0: inputs (U3.18), U_and_matrix (J1_U_and_matrix#1.R0), U_and_matrix (J1_U_and_matrix#2.R0), U_and_matrix (J1_U_and_matrix#3.R0), U_and_matrix (J1_U_and_matrix#4.R0), U_and_matrix (J1_U_and_matrix#5.R0), U_and_matrix (J1_U_and_matrix#6.R0), U_and_matrix (J1_U_and_matrix#7.R0), U_and_matrix (J1_U_and_matrix#8.R0)
in1: inputs (U3.17), U_and_matrix (J1_U_and_matrix#1.R1), U_and_matrix (J1_U_and_matrix#2.R1), U_and_matrix (J1_U_and_matrix#3.R1), U_and_matrix (J1_U_and_matrix#4.R1), U_and_matrix (J1_U_and_matrix#5.R1), U_and_matrix (J1_U_and_matrix#6.R1), U_and_matrix (J1_U_and_matrix#7.R1), U_and_matrix (J1_U_and_matrix#8.R1)
in2: inputs (U3.16), U_and_matrix (J1_U_and_matrix#1.R2), U_and_matrix (J1_U_and_matrix#2.R2), U_and_matrix (J1_U_and_matrix#3.R2), U_and_matrix (J1_U_and_matrix#4.R2), U_and_matrix (J1_U_and_matrix#5.R2), U_and_matrix (J1_U_and_matrix#6.R2), U_and_matrix (J1_U_and_matrix#7.R2), U_and_matrix (J1_U_and_matrix#8.R2)
in3: inputs (U3.15), U_and_matrix (J1_U_and_matrix#1.R3), U_and_matrix (J1_U_and_matrix#2.R3), U_and_matrix (J1_U_and_matrix#3.R3), U_and_matrix (J1_U_and_matrix#4.R3), U_and_matrix (J1_U_and_matrix#5.R3), U_and_matrix (J1_U_and_matrix#6.R3), U_and_matrix (J1_U_and_matrix#7.R3), U_and_matrix (J1_U_and_matrix#8.R3)
in4: inputs (U3.14), U_and_matrix (J1_U_and_matrix#1.R4), U_and_matrix (J1_U_and_matrix#2.R4), U_and_matrix (J1_U_and_matrix#3.R4), U_and_matrix (J1_U_and_matrix#4.R4), U_and_matrix (J1_U_and_matrix#5.R4), U_and_matrix (J1_U_and_matrix#6.R4), U_and_matrix (J1_U_and_matrix#7.R4), U_and_matrix (J1_U_and_matrix#8.R4)
in5: inputs (U3.13), U_and_matrix (J1_U_and_matrix#1.R5), U_and_matrix (J1_U_and_matrix#2.R5), U_and_matrix (J1_U_and_matrix#3.R5), U_and_matrix (J1_U_and_matrix#4.R5), U_and_matrix (J1_U_and_matrix#5.R5), U_and_matrix (J1_U_and_matrix#6.R5), U_and_matrix (J1_U_and_matrix#7.R5), U_and_matrix (J1_U_and_matrix#8.R5)
in6: inputs (U3.12), U_and_matrix (J1_U_and_matrix#1.R6), U_and_matrix (J1_U_and_matrix#2.R6), U_and_matrix (J1_U_and_matrix#3.R6), U_and_matrix (J1_U_and_matrix#4.R6), U_and_matrix (J1_U_and_matrix#5.R6), U_and_matrix (J1_U_and_matrix#6.R6), U_and_matrix (J1_U_and_matrix#7.R6), U_and_matrix (J1_U_and_matrix#8.R6)
in7: inputs (U3.11), U_and_matrix (J1_U_and_matrix#1.R7), U_and_matrix (J1_U_and_matrix#2.R7), U_and_matrix (J1_U_and_matrix#3.R7), U_and_matrix (J1_U_and_matrix#4.R7), U_and_matrix (J1_U_and_matrix#5.R7), U_and_matrix (J1_U_and_matrix#6.R7), U_and_matrix (J1_U_and_matrix#7.R7), U_and_matrix (J1_U_and_matrix#8.R7)
in8: inputs (U6.18), U_and_matrix (J2_U_and_matrix#1.R0), U_and_matrix (J2_U_and_matrix#2.R0), U_and_matrix (J2_U_and_matrix#3.R0), U_and_matrix (J2_U_and_matrix#4.R0), U_and_matrix (J2_U_and_matrix#5.R0), U_and_matrix (J2_U_and_matrix#6.R0), U_and_matrix (J2_U_and_matrix#7.R0), U_and_matrix (J2_U_and_matrix#8.R0)
in9: inputs (U6.17), U_and_matrix (J2_U_and_matrix#1.R1), U_and_matrix (J2_U_and_matrix#2.R1), U_and_matrix (J2_U_and_matrix#3.R1), U_and_matrix (J2_U_and_matrix#4.R1), U_and_matrix (J2_U_and_matrix#5.R1), U_and_matrix (J2_U_and_matrix#6.R1), U_and_matrix (J2_U_and_matrix#7.R1), U_and_matrix (J2_U_and_matrix#8.R1)
in10: inputs (U6.16), U_and_matrix (J2_U_and_matrix#1.R2), U_and_matrix (J2_U_and_matrix#2.R2), U_and_matrix (J2_U_and_matrix#3.R2), U_and_matrix (J2_U_and_matrix#4.R2), U_and_matrix (J2_U_and_matrix#5.R2), U_and_matrix (J2_U_and_matrix#6.R2), U_and_matrix (J2_U_and_matrix#7.R2), U_and_matrix (J2_U_and_matrix#8.R2)
in11: inputs (U6.15), U_and_matrix (J2_U_and_matrix#1.R3), U_and_matrix (J2_U_and_matrix#2.R3), U_and_matrix (J2_U_and_matrix#3.R3), U_and_matrix (J2_U_and_matrix#4.R3), U_and_matrix (J2_U_and_matrix#5.R3), U_and_matrix (J2_U_and_matrix#6.R3), U_and_matrix (J2_U_and_matrix#7.R3), U_and_matrix (J2_U_and_matrix#8.R3)
in12: inputs (U6.14), U_and_matrix (J2_U_and_matrix#1.R4), U_and_matrix (J2_U_and_matrix#2.R4), U_and_matrix (J2_U_and_matrix#3.R4), U_and_matrix (J2_U_and_matrix#4.R4), U_and_matrix (J2_U_and_matrix#5.R4), U_and_matrix (J2_U_and_matrix#6.R4), U_and_matrix (J2_U_and_matrix#7.R4), U_and_matrix (J2_U_and_matrix#8.R4)
in13: inputs (U6.13), U_and_matrix (J2_U_and_matrix#1.R5), U_and_matrix (J2_U_and_matrix#2.R5), U_and_matrix (J2_U_and_matrix#3.R5), U_and_matrix (J2_U_and_matrix#4.R5), U_and_matrix (J2_U_and_matrix#5.R5), U_and_matrix (J2_U_and_matrix#6.R5), U_and_matrix (J2_U_and_matrix#7.R5), U_and_matrix (J2_U_and_matrix#8.R5)
in14: inputs (U6.12), U_and_matrix (J2_U_and_matrix#1.R6), U_and_matrix (J2_U_and_matrix#2.R6), U_and_matrix (J2_U_and_matrix#3.R6), U_and_matrix (J2_U_and_matrix#4.R6), U_and_matrix (J2_U_and_matrix#5.R6), U_and_matrix (J2_U_and_matrix#6.R6), U_and_matrix (J2_U_and_matrix#7.R6), U_and_matrix (J2_U_and_matrix#8.R6)
in15: inputs (U6.11), U_and_matrix (J2_U_and_matrix#1.R7), U_and_matrix (J2_U_and_matrix#2.R7), U_and_matrix (J2_U_and_matrix#3.R7), U_and_matrix (J2_U_and_matrix#4.R7), U_and_matrix (J2_U_and_matrix#5.R7), U_and_matrix (J2_U_and_matrix#6.R7), U_and_matrix (J2_U_and_matrix#7.R7), U_and_matrix (J2_U_and_matrix#8.R7)
in16: pld_main (U10.18), U_and_matrix (J3_U_and_matrix#1.R0), U_and_matrix (J3_U_and_matrix#2.R0), U_and_matrix (J3_U_and_matrix#3.R0), U_and_matrix (J3_U_and_matrix#4.R0), U_and_matrix (J3_U_and_matrix#5.R0), U_and_matrix (J3_U_and_matrix#6.R0), U_and_matrix (J3_U_and_matrix#7.R0), U_and_matrix (J3_U_and_matrix#8.R0)
in17: pld_main (U10.17), U_and_matrix (J3_U_and_matrix#1.R1), U_and_matrix (J3_U_and_matrix#2.R1), U_and_matrix (J3_U_and_matrix#3.R1), U_and_matrix (J3_U_and_matrix#4.R1), U_and_matrix (J3_U_and_matrix#5.R1), U_and_matrix (J3_U_and_matrix#6.R1), U_and_matrix (J3_U_and_matrix#7.R1), U_and_matrix (J3_U_and_matrix#8.R1)
in18: pld_main (U10.16), U_and_matrix (J3_U_and_matrix#1.R2), U_and_matrix (J3_U_and_matrix#2.R2), U_and_matrix (J3_U_and_matrix#3.R2), U_and_matrix (J3_U_and_matrix#4.R2), U_and_matrix (J3_U_and_matrix#5.R2), U_and_matrix (J3_U_and_matrix#6.R2), U_and_matrix (J3_U_and_matrix#7.R2), U_and_matrix (J3_U_and_matrix#8.R2)
in19: pld_main (U10.15), U_and_matrix (J3_U_and_matrix#1.R3), U_and_matrix (J3_U_and_matrix#2.R3), U_and_matrix (J3_U_and_matrix#3.R3), U_and_matrix (J3_U_and_matrix#4.R3), U_and_matrix (J3_U_and_matrix#5.R3), U_and_matrix (J3_U_and_matrix#6.R3), U_and_matrix (J3_U_and_matrix#7.R3), U_and_matrix (J3_U_and_matrix#8.R3)
in20: pld_main (U10.14), U_and_matrix (J3_U_and_matrix#1.R4), U_and_matrix (J3_U_and_matrix#2.R4), U_and_matrix (J3_U_and_matrix#3.R4), U_and_matrix (J3_U_and_matrix#4.R4), U_and_matrix (J3_U_and_matrix#5.R4), U_and_matrix (J3_U_and_matrix#6.R4), U_and_matrix (J3_U_and_matrix#7.R4), U_and_matrix (J3_U_and_matrix#8.R4)
in21: pld_main (U10.13), U_and_matrix (J3_U_and_matrix#1.R5), U_and_matrix (J3_U_and_matrix#2.R5), U_and_matrix (J3_U_and_matrix#3.R5), U_and_matrix (J3_U_and_matrix#4.R5), U_and_matrix (J3_U_and_matrix#5.R5), U_and_matrix (J3_U_and_matrix#6.R5), U_and_matrix (J3_U_and_matrix#7.R5), U_and_matrix (J3_U_and_matrix#8.R5)
in22: pld_main (U10.12), U_and_matrix (J3_U_and_matrix#1.R6), U_and_matrix (J3_U_and_matrix#2.R6), U_and_matrix (J3_U_and_matrix#3.R6), U_and_matrix (J3_U_and_matrix#4.R6), U_and_matrix (J3_U_and_matrix#5.R6), U_and_matrix (J3_U_and_matrix#6.R6), U_and_matrix (J3_U_and_matrix#7.R6), U_and_matrix (J3_U_and_matrix#8.R6)
in23: pld_main (U10.11), U_and_matrix (J3_U_and_matrix#1.R7), U_and_matrix (J3_U_and_matrix#2.R7), U_and_matrix (J3_U_and_matrix#3.R7), U_and_matrix (J3_U_and_matrix#4.R7), U_and_matrix (J3_U_and_matrix#5.R7), U_and_matrix (J3_U_and_matrix#6.R7), U_and_matrix (J3_U_and_matrix#7.R7), U_and_matrix (J3_U_and_matrix#8.R7)
in24: pld_main (U12.18), U_and_matrix (J4_U_and_matrix#1.R0), U_and_matrix (J4_U_and_matrix#2.R0), U_and_matrix (J4_U_and_matrix#3.R0), U_and_matrix (J4_U_and_matrix#4.R0), U_and_matrix (J4_U_and_matrix#5.R0), U_and_matrix (J4_U_and_matrix#6.R0), U_and_matrix (J4_U_and_matrix#7.R0), U_and_matrix (J4_U_and_matrix#8.R0)
in25: pld_main (U12.17), U_and_matrix (J4_U_and_matrix#1.R1), U_and_matrix (J4_U_and_matrix#2.R1), U_and_matrix (J4_U_and_matrix#3.R1), U_and_matrix (J4_U_and_matrix#4.R1), U_and_matrix (J4_U_and_matrix#5.R1), U_and_matrix (J4_U_and_matrix#6.R1), U_and_matrix (J4_U_and_matrix#7.R1), U_and_matrix (J4_U_and_matrix#8.R1)
in26: pld_main (U12.16), U_and_matrix (J4_U_and_matrix#1.R2), U_and_matrix (J4_U_and_matrix#2.R2), U_and_matrix (J4_U_and_matrix#3.R2), U_and_matrix (J4_U_and_matrix#4.R2), U_and_matrix (J4_U_and_matrix#5.R2), U_and_matrix (J4_U_and_matrix#6.R2), U_and_matrix (J4_U_and_matrix#7.R2), U_and_matrix (J4_U_and_matrix#8.R2)
in27: pld_main (U12.15), U_and_matrix (J4_U_and_matrix#1.R3), U_and_matrix (J4_U_and_matrix#2.R3), U_and_matrix (J4_U_and_matrix#3.R3), U_and_matrix (J4_U_and_matrix#4.R3), U_and_matrix (J4_U_and_matrix#5.R3), U_and_matrix (J4_U_and_matrix#6.R3), U_and_matrix (J4_U_and_matrix#7.R3), U_and_matrix (J4_U_and_matrix#8.R3)
in28: pld_main (U12.14), U_and_matrix (J4_U_and_matrix#1.R4), U_and_matrix (J4_U_and_matrix#2.R4), U_and_matrix (J4_U_and_matrix#3.R4), U_and_matrix (J4_U_and_matrix#4.R4), U_and_matrix (J4_U_and_matrix#5.R4), U_and_matrix (J4_U_and_matrix#6.R4), U_and_matrix (J4_U_and_matrix#7.R4), U_and_matrix (J4_U_and_matrix#8.R4)
in29: pld_main (U12.13), U_and_matrix (J4_U_and_matrix#1.R5), U_and_matrix (J4_U_and_matrix#2.R5), U_and_matrix (J4_U_and_matrix#3.R5), U_and_matrix (J4_U_and_matrix#4.R5), U_and_matrix (J4_U_and_matrix#5.R5), U_and_matrix (J4_U_and_matrix#6.R5), U_and_matrix (J4_U_and_matrix#7.R5), U_and_matrix (J4_U_and_matrix#8.R5)
in30: pld_main (U12.12), U_and_matrix (J4_U_and_matrix#1.R6), U_and_matrix (J4_U_and_matrix#2.R6), U_and_matrix (J4_U_and_matrix#3.R6), U_and_matrix (J4_U_and_matrix#4.R6), U_and_matrix (J4_U_and_matrix#5.R6), U_and_matrix (J4_U_and_matrix#6.R6), U_and_matrix (J4_U_and_matrix#7.R6), U_and_matrix (J4_U_and_matrix#8.R6)
in31: pld_main (U12.11), U_and_matrix (J4_U_and_matrix#1.R7), U_and_matrix (J4_U_and_matrix#2.R7), U_and_matrix (J4_U_and_matrix#3.R7), U_and_matrix (J4_U_and_matrix#4.R7), U_and_matrix (J4_U_and_matrix#5.R7), U_and_matrix (J4_U_and_matrix#6.R7), U_and_matrix (J4_U_and_matrix#7.R7), U_and_matrix (J4_U_and_matrix#8.R7)
NetR9_U_and_matrix#1_2: pld_main (U5#1.11), U_and_matrix (9 pins)
NetR9_U_and_matrix#2_2: pld_main (U8.3), U_and_matrix (9 pins)
NetR9_U_and_matrix#3_2: pld_main (U8.5), U_and_matrix (9 pins)
NetR9_U_and_matrix#4_2: pld_main (U8.13), U_and_matrix (9 pins)
NetR9_U_and_matrix#5_2: pld_main (U11.1), U_and_matrix (9 pins)
NetR9_U_and_matrix#6_2: pld_main (U11.9), U_and_matrix (9 pins)
NetR9_U_and_matrix#7_2: pld_main (U11.11), U_and_matrix (9 pins)
NetR9_U_and_matrix#8_2: pld_main (U13.3), U_and_matrix (9 pins)
rst: pld_main (U7.9 U9.9), inputs (U5#1.6 U5#1.9)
